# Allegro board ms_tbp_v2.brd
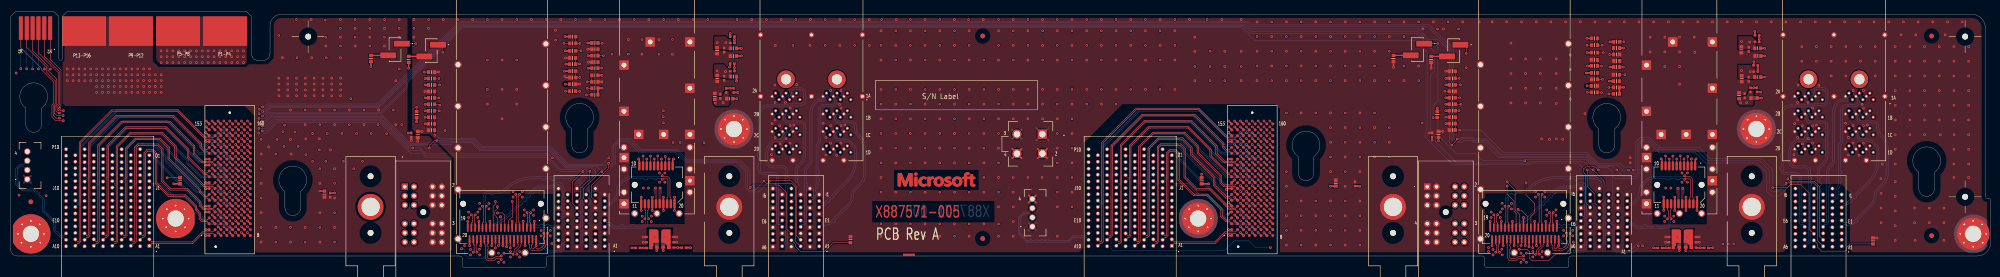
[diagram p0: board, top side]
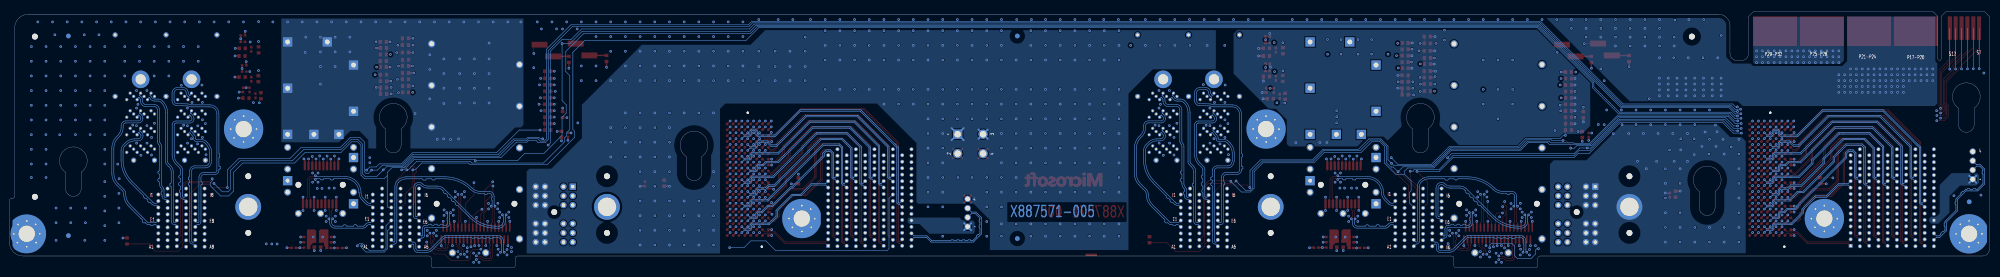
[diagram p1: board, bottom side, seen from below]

Outline 428 x 55.34 mm; copper layers: TOP, LYR2, LYR3, LYR4, LYR5, LYR6, LYR7, BOTTOM. Coordinates in mm from the lower left corner of the outline.
Outline path: 0,54.34 0,4.04 arc(0.44,2.98) 1.5,2.54 97.13,2.54 arc(97.49,2.39) 97.64,2.04 97.64,0.5 arc(97.78,0.15) 98.14,0 115.29,0 arc(115.64,0.15) 115.79,0.5 115.79,2.04 arc(115.93,2.39) 116.28,2.54 318.13,2.54 arc(318.49,2.39) 318.64,2.04 318.64,0.5 arc(318.78,0.15) 319.14,0 336.29,0 arc(336.64,0.15) 336.79,0.5 336.79,2.04 arc(336.93,2.39) 337.28,2.54 425,2.54 arc(427.12,3.42) 428,5.54 428,14.5 arc(427.85,14.85) 427.5,15 427.34,15 arc(426.99,15.15) 426.84,15.5 426.84,51.84 arc(425.96,53.96) 423.84,54.84 58.58,54.84 arc(56.81,54.11) 56.08,52.34 56.08,46.34 arc(55.64,45.28) 54.58,44.84 53.58,44.84 arc(52.52,45.28) 52.08,46.34 52.08,54.34 51.08,55.34 12.15,55.34 11.15,54.34 11.15,45.19 arc(10.8,44.84) 10.45,45.19 10.45,54.34 9.45,55.34 1,55.34 0,54.34 ; 3.3,34.53 arc(5,40) 6.7,34.53 6.7,31 arc(5,29.3) 3.3,31 3.3,34.53 ; 59.3,16.53 arc(61,22) 62.7,16.53 62.7,13 arc(61,11.3) 59.3,13 59.3,16.53 ; 121.3,30.07 arc(123,35.54) 124.7,30.07 124.7,26.54 arc(123,24.84) 121.3,26.54 121.3,30.07 ; 278.3,24.07 arc(280,29.54) 281.7,24.07 281.7,20.54 arc(280,18.84) 278.3,20.54 278.3,24.07 ; 343.3,30.07 arc(345,35.54) 346.7,30.07 346.7,26.54 arc(345,24.84) 343.3,26.54 343.3,30.07 ; 412.45,20.67 arc(414.15,26.14) 415.85,20.67 415.85,17.14 arc(414.15,15.44) 412.45,17.14 412.45,20.67

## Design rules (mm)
constraint set DEFAULT: min track width 0.102
net group DP_CLK_100M_B1<0>: nets CLK_100M_B1_N<0> CLK_100M_B1_P<0>
net group DP_CLK_100M_B1<1>: nets CLK_100M_B1_N<1> CLK_100M_B1_P<1>
net group DP_CLK_100M_B1<2>: nets CLK_100M_B1_N<2> CLK_100M_B1_P<2>
net group DP_CLK_100M_B1<3>: nets CLK_100M_B1_N<3> CLK_100M_B1_P<3>
net group DP_CLK_100M_B2<0>: nets CLK_100M_B2_N<0> CLK_100M_B2_P<0>
net group DP_CLK_100M_B2<1>: nets CLK_100M_B2_N<1> CLK_100M_B2_P<1>
net group DP_CLK_100M_B2<2>: nets CLK_100M_B2_N<2> CLK_100M_B2_P<2>
net group DP_CLK_100M_B2<3>: nets CLK_100M_B2_N<3> CLK_100M_B2_P<3>
net group DP_ETH10G_B1_RX: nets ETH10G_B1_RXN ETH10G_B1_RXP
net group DP_ETH10G_B1_TX2: nets ETH10G_B1_TXN ETH10G_B1_TXP
net group DP_ETH10G_B2_RX: nets ETH10G_B2_RXN ETH10G_B2_RXP
net group DP_ETH10G_B2_TX2: nets ETH10G_B2_TXN ETH10G_B2_TXP
net group DP_PCIE_B2T_B1_TX_D<0>: nets PCIE_B2T_B1_TX_DN<0> PCIE_B2T_B1_TX_DP<0>
net group DP_PCIE_B2T_B1_TX_D<1>: nets PCIE_B2T_B1_TX_DN<1> PCIE_B2T_B1_TX_DP<1>
net group DP_PCIE_B2T_B1_TX_D<2>: nets PCIE_B2T_B1_TX_DN<2> PCIE_B2T_B1_TX_DP<2>
net group DP_PCIE_B2T_B1_TX_D<3>: nets PCIE_B2T_B1_TX_DN<3> PCIE_B2T_B1_TX_DP<3>
net group DP_PCIE_B2T_B1_TX_D<4>: nets PCIE_B2T_B1_TX_DN<4> PCIE_B2T_B1_TX_DP<4>
net group DP_PCIE_B2T_B1_TX_D<5>: nets PCIE_B2T_B1_TX_DN<5> PCIE_B2T_B1_TX_DP<5>
net group DP_PCIE_B2T_B1_TX_D<6>: nets PCIE_B2T_B1_TX_DN<6> PCIE_B2T_B1_TX_DP<6>
net group DP_PCIE_B2T_B1_TX_D<7>: nets PCIE_B2T_B1_TX_DN<7> PCIE_B2T_B1_TX_DP<7>
net group DP_PCIE_B2T_B1_TX_D<8>: nets PCIE_B2T_B1_TX_DN<8> PCIE_B2T_B1_TX_DP<8>
net group DP_PCIE_B2T_B1_TX_D<10>: nets PCIE_B2T_B1_TX_DN<10> PCIE_B2T_B1_TX_DP<10>
net group DP_PCIE_B2T_B1_TX_D<12>: nets PCIE_B2T_B1_TX_DN<12> PCIE_B2T_B1_TX_DP<12>
net group DP_PCIE_B2T_B1_TX_D<14>: nets PCIE_B2T_B1_TX_DN<14> PCIE_B2T_B1_TX_DP<14>
net group DP_PCIE_B2T_B2_TX_D<8>: nets PCIE_B2T_B2_TX_DN<8> PCIE_B2T_B2_TX_DP<8>
net group DP_PCIE_B2T_B2_TX_D<9>: nets PCIE_B2T_B2_TX_DN<9> PCIE_B2T_B2_TX_DP<9>
net group DP_PCIE_B2T_B2_TX_D<10>: nets PCIE_B2T_B2_TX_DN<10> PCIE_B2T_B2_TX_DP<10>
net group DP_PCIE_B2T_B2_TX_D<11>: nets PCIE_B2T_B2_TX_DN<11> PCIE_B2T_B2_TX_DP<11>
net group DP_PCIE_B2T_B2_TX_D<12>: nets PCIE_B2T_B2_TX_DN<12> PCIE_B2T_B2_TX_DP<12>
net group DP_PCIE_B2T_B2_TX_D<13>: nets PCIE_B2T_B2_TX_DN<13> PCIE_B2T_B2_TX_DP<13>
net group DP_PCIE_B2T_B2_TX_D<14>: nets PCIE_B2T_B2_TX_DN<14> PCIE_B2T_B2_TX_DP<14>
net group DP_PCIE_B2T_B2_TX_D<15>: nets PCIE_B2T_B2_TX_DN<15> PCIE_B2T_B2_TX_DP<15>
net group DP_PCIE_T2B_B1_RX_D<0>: nets PCIE_T2B_B1_RX_DN<0> PCIE_T2B_B1_RX_DP<0>
net group DP_PCIE_T2B_B1_RX_D<3>: nets PCIE_T2B_B1_RX_DN<3> PCIE_T2B_B1_RX_DP<3>
net group DP_PCIE_T2B_B1_RX_D<8>: nets PCIE_T2B_B1_RX_DN<8> PCIE_T2B_B1_RX_DP<8>
net group DP_PCIE_T2B_B1_RX_D<15>: nets PCIE_T2B_B1_RX_DN<15> PCIE_T2B_B1_RX_DP<15>
net group DP_PCIE_T2B_B2_RX_D<0>: nets PCIE_T2B_B2_RX_DN<0> PCIE_T2B_B2_RX_DP<0>
net group DP_PCIE_T2B_B2_RX_D<2>: nets PCIE_T2B_B2_RX_DN<2> PCIE_T2B_B2_RX_DP<2>
net group DP_PCIE_T2B_B2_RX_D<4>: nets PCIE_T2B_B2_RX_DN<4> PCIE_T2B_B2_RX_DP<4>
net group DP_PCIE_T2B_B2_RX_D<6>: nets PCIE_T2B_B2_RX_DN<6> PCIE_T2B_B2_RX_DP<6>
net group DP_PCIE_T2B_B2_RX_D<8>: nets PCIE_T2B_B2_RX_DN<8> PCIE_T2B_B2_RX_DP<8>
net group DP_PCIE_T2B_B2_RX_D<9>: nets PCIE_T2B_B2_RX_DN<9> PCIE_T2B_B2_RX_DP<9>
net group DP_PCIE_T2B_B2_RX_D<10>: nets PCIE_T2B_B2_RX_DN<10> PCIE_T2B_B2_RX_DP<10>
net group DP_PCIE_T2B_B2_RX_D<12>: nets PCIE_T2B_B2_RX_DN<12> PCIE_T2B_B2_RX_DP<12>
net group DP_PCIE_T2B_B2_RX_D<13>: nets PCIE_T2B_B2_RX_DN<13> PCIE_T2B_B2_RX_DP<13>
net group DP_PCIE_T2B_B2_RX_D<14>: nets PCIE_T2B_B2_RX_DN<14> PCIE_T2B_B2_RX_DP<14>
net group DP_PCIE_T2B_B2_RX_D<15>: nets PCIE_T2B_B2_RX_DN<15> PCIE_T2B_B2_RX_DP<15>
net group MG_SAS_B1_RX1: nets SAS_B1_RX1N SAS_B1_RX1P
net group MG_SAS_B1_TX1: nets SAS_B1_TX3N SAS_B1_TX3P
net group USB_B1: nets USB_B1_N USB_B1_P
net group USB_B2: nets USB_B2_N USB_B2_P
net group BLADE_B1_MATED_N: nets BLADE_B1_MATED_N<1>
net group BLADE_B2_MATED_N: nets BLADE_B2_MATED_N
net group BLADE_MATED_B1_N: nets BLADE_MATED_B1_N<0>
net group BLADE_MATED_B2_N: nets BLADE_MATED_B2_N<0>
net group DP_ETH40G_B2_RX0: nets ETH40G_B2_RX0N
net group MG_ETH40G_B1_RX: nets ETH40G_B1_RX0N ETH40G_B1_RX0P ETH40G_B1_RX1N ETH40G_B1_RX1P ETH40G_B1_RX2N ETH40G_B1_RX2P ETH40G_B1_RX3N ETH40G_B1_RX3P
net group MG_ETH40G_B1_TX: nets ETH40G_B1_TX0N ETH40G_B1_TX0P ETH40G_B1_TX1N ETH40G_B1_TX1P ETH40G_B1_TX2N ETH40G_B1_TX2P ETH40G_B1_TX3N ETH40G_B1_TX3P
net group MG_ETH40G_B2_RX: nets ETH40G_B2_RX0P ETH40G_B2_RX1N ETH40G_B2_RX1P ETH40G_B2_RX2N ETH40G_B2_RX2P ETH40G_B2_RX3N ETH40G_B2_RX3P
net group MG_ETH40G_B2_TX: nets ETH40G_B2_TX0N ETH40G_B2_TX0P ETH40G_B2_TX1N ETH40G_B2_TX1P ETH40G_B2_TX2N ETH40G_B2_TX2P ETH40G_B2_TX3N ETH40G_B2_TX3P
net group MG_PCIE_B2T_B1_TX: nets PCIE_B2T_B1_TX_DN<9> PCIE_B2T_B1_TX_DN<11> PCIE_B2T_B1_TX_DN<13> PCIE_B2T_B1_TX_DN<15> PCIE_B2T_B1_TX_DP<9> PCIE_B2T_B1_TX_DP<11> PCIE_B2T_B1_TX_DP<13> PCIE_B2T_B1_TX_DP<15>
net group MG_PCIE_B2T_B2_TX: nets PCIE_B2T_B2_TX_DN<0> PCIE_B2T_B2_TX_DN<1> PCIE_B2T_B2_TX_DN<2> PCIE_B2T_B2_TX_DN<3> PCIE_B2T_B2_TX_DN<4> PCIE_B2T_B2_TX_DN<5> PCIE_B2T_B2_TX_DN<6> PCIE_B2T_B2_TX_DN<7> PCIE_B2T_B2_TX_DP<0> PCIE_B2T_B2_TX_DP<1> PCIE_B2T_B2_TX_DP<2> PCIE_B2T_B2_TX_DP<3> PCIE_B2T_B2_TX_DP<4> PCIE_B2T_B2_TX_DP<5> PCIE_B2T_B2_TX_DP<6> PCIE_B2T_B2_TX_DP<7>
net group MG_PCIE_T2B_B1_RX: nets PCIE_T2B_B1_RX_DN<1> PCIE_T2B_B1_RX_DN<2> PCIE_T2B_B1_RX_DN<4> PCIE_T2B_B1_RX_DN<5> PCIE_T2B_B1_RX_DN<6> PCIE_T2B_B1_RX_DN<7> PCIE_T2B_B1_RX_DN<9> PCIE_T2B_B1_RX_DN<10> PCIE_T2B_B1_RX_DN<11> PCIE_T2B_B1_RX_DN<12> PCIE_T2B_B1_RX_DN<13> PCIE_T2B_B1_RX_DN<14> PCIE_T2B_B1_RX_DP<1> PCIE_T2B_B1_RX_DP<2> PCIE_T2B_B1_RX_DP<4> PCIE_T2B_B1_RX_DP<5> PCIE_T2B_B1_RX_DP<6> PCIE_T2B_B1_RX_DP<7> PCIE_T2B_B1_RX_DP<9> PCIE_T2B_B1_RX_DP<10> PCIE_T2B_B1_RX_DP<11> PCIE_T2B_B1_RX_DP<12> PCIE_T2B_B1_RX_DP<13> PCIE_T2B_B1_RX_DP<14>
net group MG_PCIE_T2B_B2_RX: nets PCIE_T2B_B2_RX_DN<1> PCIE_T2B_B2_RX_DN<3> PCIE_T2B_B2_RX_DN<5> PCIE_T2B_B2_RX_DN<7> PCIE_T2B_B2_RX_DN<11> PCIE_T2B_B2_RX_DP<1> PCIE_T2B_B2_RX_DP<3> PCIE_T2B_B2_RX_DP<5> PCIE_T2B_B2_RX_DP<7> PCIE_T2B_B2_RX_DP<11>
net group MG_SAS_B1_RX2: nets SAS_B1_RX6N SAS_B1_RX6P SAS_B1_RX7N SAS_B1_RX7P
net group MG_SAS_B2_RX1: nets SAS_B2_RX1N SAS_B2_RX1P SAS_B2_RX2N SAS_B2_RX2P SAS_B2_RX3N SAS_B2_RX3P SAS_B2_RX4N SAS_B2_RX4P
net group MG_SAS_B2_RX2: nets SAS_B2_RX5N SAS_B2_RX5P SAS_B2_RX6N SAS_B2_RX6P SAS_B2_RX7N SAS_B2_RX7P SAS_B2_RX8N SAS_B2_RX8P
net group MG_SAS_B2_TX1: nets SAS_B2_TX1N SAS_B2_TX1P SAS_B2_TX2N SAS_B2_TX2P SAS_B2_TX3N SAS_B2_TX3P SAS_B2_TX4N SAS_B2_TX4P
net group MG_SAS_B2_TX2: nets SAS_B2_TX5N SAS_B2_TX5P SAS_B2_TX6N SAS_B2_TX6P SAS_B2_TX7N SAS_B2_TX7P SAS_B2_TX8N SAS_B2_TX8P
net group PCIE_RESET_B1_N: nets PCIE_RESET_B1_N<0> PCIE_RESET_B1_N<1> PCIE_RESET_B1_N<2> PCIE_RESET_B1_N<3>
net group PCIE_RESET_B2_N: nets PCIE_RESET_B2_N<0> PCIE_RESET_B2_N<1> PCIE_RESET_B2_N<2> PCIE_RESET_B2_N<3>

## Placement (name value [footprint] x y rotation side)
C1  -  [CAP_0603_CO]  88.01 28.83 90 top
C2  -  [CAP_0603_CO]  67.85 15.94 90 top
C3  -  [CAP_0402_CO]  69.07 15.71 90 top
C4  -  [CAP_0402_CO]  86.61 28.7 90 top
C5  -  [CAP_0402_CO]  142.85 6.65 0 top
C6  -  [CAP_0402_CO]  142.85 5.51 0 top
C7  -  [CAP_0402_CO]  137.9 6.65 180 top
C8  -  [CAP_0402_CO]  137.9 5.51 180 top
C9  -  [CAP_0402_CO]  363.85 6.65 0 top
C10  -  [CAP_0402_CO]  363.85 5.51 0 top
C11  -  [CAP_0402_CO]  358.9 6.65 180 top
C12  -  [CAP_0402_CO]  358.9 5.51 180 top
C13  -  [CAP_0603_CO]  308.64 28.85 90 top
C14  -  [CAP_0603_CO]  286.44 18.3 90 top
C15  -  [CAP_0402_CO]  307.24 28.73 90 top
C16  -  [CAP_0402_CO]  290.58 18.12 90 top
C17  -  [CAP_0402_CO]  374.8 37.21 90 top
C18  -  [CAP_0603_CO]  373.6 37.21 90 top
C19  -  [CAP_0402_CO]  375.69 40.77 270 top
C20  -  [CAP_0402_CO]  375.69 47.24 270 top
C23  -  [CAP_0603_CO]  374.17 40.88 270 top
C24  -  [CAP_0603_CO]  374.1 47.13 270 top
C27  -  [CAP_0603_CO]  377.68 45.81 180 top
C29  -  [CAP_0402_CO]  153.42 37.08 90 top
C30  -  [CAP_0603_CO]  152.22 37.08 90 top
C31  -  [CAP_0402_CO]  154.24 40.98 270 top
C32  -  [CAP_0402_CO]  154.24 47.08 270 top
C35  -  [CAP_0603_CO]  152.74 40.96 270 top
C36  -  [CAP_0603_CO]  152.71 46.95 270 top
C39  -  [CAP_0603_CO]  156.24 45.78 180 top
FB1  -  [FB_0402_CO]  137.98 4.28 0 top
FB2  -  [FB_0402_CO]  142.85 4.37 0 top
FB3  -  [FB_0402_CO]  358.99 4.28 0 top
FB4  -  [FB_0402_CO]  363.85 4.37 0 top
FB5  -  [FB_0402_CO]  377.21 42.42 180 top
FB6  -  [FB_0402_CO]  377.5 48.86 180 top
FB7  -  [FB_0402_CO]  376.07 38.48 90 top
FB8  -  [FB_0402_CO]  156.01 42.53 180 top
FB9  -  [FB_0402_CO]  156.01 48.63 180 top
FB10  -  [FB_0402_CO]  154.69 38.35 90 top
FS1  -  [RES_0402_CO]  135.57 4.31 0 top
FS2  -  [RES_0402_CO]  145.52 4.36 0 top
FS3  -  [RES_0402_CO]  356.5 4.28 0 top
FS4  -  [RES_0402_CO]  366.53 4.31 0 top
FS5  -  [RES_0402_CO]  377.2 43.78 0 top
FS6  -  [RES_0402_CO]  377.5 50.25 0 top
FS7  -  [RES_0402_CO]  377.46 38.48 270 top
FS8  -  [RES_0402_CO]  155.99 44.16 0 top
FS9  -  [RES_0402_CO]  156.01 50 0 top
FS10  -  [RES_0402_CO]  156.27 38.37 270 top
J1  -  [CONN_RCPT_AIRMAX_155P_35P8X19P9X20P05_2MM_RT]  30 4.74 180 top
J2  -  [CONN_RCPT_160P_8X20_32P05X10P74X6P68_1P27MM_CO]  47.38 19.04 90 top
J3  -  [GUIDEPIN_53P53X10P65X14P8MM_RT]  77.81 13.17 180 top
J4  -  [CONN_RCPT_AIRMAX_24P_29P3X11P85X10P5_2MM_RT]  85.21 17.54 0 top
J5  -  [CONN_RCPT_SFP_20P_11X7P7X5P45_P8MM_CO_RT]  139.71 17.94 180 top
J6  -  [CONN_HSNG_SFP_20P_48P72X16P2X10P05MM]  139.71 17.94 180 top
J7  -  [CONN_RCPT_AIRMAX_57P_27P3X11P9X11P65_2MM_RT]  128.42 4.64 180 top
J8  -  [CONN_RCPT_SFP_38P_18P2X11P5X5P48_P8MM_CO_RT]  106.21 10.99 180 top
J9  -  [CONN_HSNG_SFP_12P_58P72X21P95X14P1MM]  106.21 10.99 180 top
J10  -  [GUIDEPIN_53P53X10P65X14P8MM_RT]  155.35 13.17 180 top
J11  -  [CONN_RCPT_AIRMAX_57P_27P3X11P9X11P65_2MM_RT]  174.78 4.64 180 top
J12  -  [CONN_MINI_SAS_82P_38X22P25X12P24MM_RT]  181.61 36.36 180 top
J13  -  [CONN_RCPT_AIRMAX_155P_35P8X19P9X20P05_2MM_RT]  251 4.74 180 top
J14  -  [CONN_RCPT_160P_8X20_32P05X10P74X6P68_1P27MM_CO]  268.38 19.04 90 top
J15  -  [GUIDEPIN_53P53X10P65X14P8MM_RT]  298.81 13.17 180 top
J16  -  [CONN_RCPT_AIRMAX_24P_29P3X11P85X10P5_2MM_RT]  306.21 17.54 0 top
J17  -  [CONN_RCPT_SFP_20P_11X7P7X5P45_P8MM_CO_RT]  360.71 17.94 180 top
J18  -  [CONN_HSNG_SFP_20P_48P72X16P2X10P05MM]  360.71 17.94 180 top
J19  -  [CONN_RCPT_AIRMAX_57P_27P3X11P9X11P65_2MM_RT]  349.42 4.64 180 top
J20  -  [CONN_RCPT_SFP_38P_18P2X11P5X5P48_P8MM_CO_RT]  327.21 10.99 180 top
J21  -  [CONN_HSNG_SFP_12P_58P72X21P95X14P1MM]  327.21 10.99 180 top
J22  -  [GUIDEPIN_53P53X10P65X14P8MM_RT]  376.35 13.17 180 top
J23  -  [CONN_RCPT_AIRMAX_57P_27P3X11P9X11P65_2MM_RT]  395.78 4.64 180 top
J24  -  [CONN_MINI_SAS_82P_38X22P25X12P24MM_RT]  402.61 36.36 180 top
J25  -  [CONN_HDR_2P_1X2_5P08X2P54X9P65_2P54MM_CO]  90.91 46.98 270 top
J26  -  [CONN_HDR_2P_1X2_5P08X2P54X9P65_2P54MM_CO]  83.09 47.21 270 top
J27  -  [CONN_HDR_4P_2X2_9P6X9P6X12P8_4P2MM]  223.02 28.89 270 top
J28  -  [CONN_HDR_2P_1X2_5P08X2P54X9P65_2P54MM_CO]  311.91 46.98 270 top
J29  -  [CONN_HDR_2P_1X2_5P08X2P54X9P65_2P54MM_CO]  304.09 47.21 270 top
MH1  -  [MTG_276P138_VIA_9P]  4.4 7.34 0 top
MH2  -  [MTG_276P138_VIA_9P]  35.69 10.64 0 top
MH3  -  [MTG_276P138_VIA_9P]  156.35 30 0 top
MH4  -  [MTG_276P138_VIA_9P]  256.69 10.64 0 top
MH5  -  [MTG_276P138_VIA_9P]  377.35 30 0 top
MH6  -  [MTG_276P138_VIA_9P]  424.21 7.34 0 top
NOREF  -  [unnamed]  422.46 15.34 0 top
NOREF#2  -  [#2]  -8.96 317.97 0 top
NOREF#3  -  [#2]  0.03 4.71 0 top
NOREF#4  -  [unnamed]  210.12 50.13 0 top
NOREF#5  -  [#2]  10.81 44.84 0 top
NOREF#6  -  [#2]  10.45 54.34 0 top
NOREF#7  -  [#2]  280 26.54 0 top
NOREF#8  -  [#2]  428 5.54 0 top
NOREF#9  -  [unnamed]  64.32 50 0 top
NOREF#10  -  [#2]  352.18 0.3 0 top
NOREF#11  -  [#2]  534.27 145.48 0 top
NOREF#12  -  [#2]  426.5 2.54 0 top
NOREF#13  -  [unnamed]  415.22 50.13 0 top
NOREF#14  -  [#2]  369.79 0 0 top
NOREF#15  -  [#2]  318.65 1.33 0 top
NOREF#16  -  [#2]  530.41 318.63 0 top
NOREF#17  -  [#2]  11.15 54.34 0 top
NOREF#18  -  [#2]  524.06 304 0 top
NOREF#19  -  [#2]  336.74 1.1 0 top
NOREF#20  -  [#2]  345 31.54 0 top
NOREF#21  -  [#2]  97.64 1.03 0 top
NOREF#22  -  [#2]  5 37 0 top
NOREF#23  -  [#2]  427.56 53.76 0 top
NOREF#24  -  [#2]  5 24 0 top
NOREF#25  -  [#2]  56.08 52.34 0 top
NOREF#26  -  [#2]  61 19 0 top
NOREF#27  -  [#2]  384.6 220.41 0 top
NOREF#28  -  [#2]  427.91 14.78 0 top
NOREF#29  -  [#2]  17.11 55.39 0 top
NOREF#30  -  [#2]  191.86 17.52 0 top
NOREF#31  -  [#2]  280 26.54 0 top
NOREF#32  -  [#2]  115.78 1.03 0 top
NOREF#33  -  [#2]  422.46 50 0 top
NOREF#34  -  [#2]  0.72 55.06 0 top
NOREF#35  -  [#2]  56.61 53.88 0 top
NOREF#36  -  [#2]  -60.14 -153.2 0 top
NOREF#37  -  [#2]  422.46 50 0 top
NOREF#38  -  [unnamed]  210.12 6.31 0 top
NOREF#39  -  [#2]  262.59 48.05 0 top
NOREF#40  -  [#2]  425.5 54.84 0 top
NOREF#41  -  [#2]  414.15 23.14 0 top
NOREF#42  -  [#2]  61 19 0 top
NOREF#43  -  [#2]  1 55.34 0 top
NOREF#44  -  [#2]  117.66 -102.4 0 top
NOREF#45  -  [#2]  533.1 -27.1 0 top
NOREF#46  -  [#2]  414.15 21.14 0 top
NOREF#47  -  [#2]  52.65 45.16 0 top
NOREF#48  -  [#2]  123 31.54 0 top
NOREF#49  -  [#2]  149.43 2.39 0 top
NOREF#50  -  [#2]  426.84 51.84 0 top
NOREF#51  -  [#2]  52.08 54.34 0 top
NOREF#52  -  [#2]  123 32.54 0 top
NOREF#53  -  [#2]  397.3 220.41 0 top
NOREF#54  -  [unnamed]  415.22 6.95 0 top
NOREF#55  -  [#2]  10.92 44.86 0 top
NOREF#56  -  [unnamed]  422.46 50 0 top
NOREF#57  -  [unnamed]  4.38 14.26 0 top
NOREF#58  -  [#2]  422.46 15.34 0 top
NOREF#59  -  [unnamed]  210.12 50.13 180 bottom
NOREF#60  -  [unnamed]  4.38 14.26 180 bottom
NOREF#61  -  [unnamed]  210.12 6.31 180 bottom
NOREF#62  -  [unnamed]  415.22 6.95 180 bottom
NOREF#63  -  [unnamed]  415.22 50.13 180 bottom
R1  -  [RES_0603_CO]  181.54 6.06 270 top
R2  -  [RES_0603_CO]  126.3 41.62 180 top
R3  -  [RES_0603_CO]  126.3 40.22 0 top
R4  -  [RES_0603_CO]  121.52 42.53 0 top
R5  -  [RES_0603_CO]  121.52 41.14 180 top
R6  -  [RES_0603_CO]  90.99 31.15 0 top
R7  -  [RES_0603_CO]  90.99 29.76 180 top
R9  -  [RES_0603_CO]  86.04 45.07 270 top
R11  -  [RES_0603_CO]  77.91 45.28 270 top
R12  -  [RES_0603_CO]  121.47 39.71 0 top
R13  -  [RES_0603_CO]  139.67 5.13 90 top
R15  -  [RES_0603_CO]  121.52 48.53 0 top
R17  -  [RES_0603_CO]  141.07 5.13 270 top
R18  -  [RES_0603_CO]  126.31 48.62 0 top
R20  -  [RES_0603_CO]  126.31 45.87 0 top
R21  -  [RES_0603_CO]  126.31 47.27 180 top
R22  -  [RES_0603_CO]  126.31 43.15 0 top
R23  -  [RES_0603_CO]  126.31 44.48 180 top
R24  -  [RES_0603_CO]  121.49 44.04 0 top
R25  -  [RES_0603_CO]  121.49 45.36 180 top
R26  -  [RES_0603_CO]  126.3 37.43 180 top
R27  -  [RES_0603_CO]  121.51 46.92 0 top
R28  -  [RES_0603_CO]  126.3 38.82 180 top
R29  -  [RES_0603_CO]  121.52 50 180 top
R30  -  [RES_0603_CO]  342.34 43.66 0 top
R31  -  [RES_0603_CO]  342.34 44.98 180 top
R32  -  [RES_0603_CO]  342.37 42.15 0 top
R33  -  [RES_0603_CO]  342.37 40.75 180 top
R34  -  [RES_0603_CO]  311.61 31.18 0 top
R35  -  [RES_0603_CO]  311.61 29.78 180 top
R37  -  [RES_0603_CO]  307.04 45.07 270 top
R39  -  [RES_0603_CO]  298.91 45.28 270 top
R40  -  [RES_0603_CO]  342.32 39.33 0 top
R41  -  [RES_0603_CO]  360.67 5.13 90 top
R43  -  [RES_0603_CO]  342.37 48.15 0 top
R45  -  [RES_0603_CO]  362.07 5.13 270 top
R46  -  [RES_0603_CO]  347.17 48.87 0 top
R48  -  [RES_0603_CO]  347.17 43.41 0 top
R49  -  [RES_0603_CO]  347.17 44.73 180 top
R50  -  [RES_0603_CO]  347.1 40.35 0 top
R51  -  [RES_0603_CO]  347.1 41.74 180 top
R52  -  [RES_0603_CO]  347.13 47.52 180 top
R53  -  [RES_0603_CO]  347.13 46.13 0 top
R54  -  [RES_0603_CO]  347.1 37.6 180 top
R55  -  [RES_0603_CO]  342.36 46.54 0 top
R56  -  [RES_0603_CO]  347.1 39 180 top
R57  -  [RES_0603_CO]  342.37 49.62 180 top
R58  -  [RES_0603_CO]  377.65 41.24 180 top
R59  -  [RES_0603_CO]  377.63 47.46 180 top
R60  -  [RES_0603_CO]  376.83 36.7 0 top
R61  -  [RES_0603_CO]  311.61 32.58 180 top
R62  -  [RES_0603_CO]  311.61 40.96 0 top
R63  -  [RES_0603_CO]  311.61 42.51 180 top
R64  -  [RES_0603_CO]  311.61 36.77 0 top
R65  -  [RES_0603_CO]  311.61 38.16 0 top
R66  -  [RES_0603_CO]  342.32 37.93 0 top
R67  -  [RES_0603_CO]  311.61 33.97 0 top
R68  -  [RES_0603_CO]  311.61 35.37 0 top
R69  -  [RES_0603_CO]  311.61 39.56 0 top
R70  -  [RES_0603_CO]  308.39 33.13 270 top
R71  -  [RES_0603_CO]  402.55 5.8 270 top
R72  -  [RES_0603_CO]  156.27 41.36 180 top
R73  -  [RES_0603_CO]  156.27 47.46 180 top
R74  -  [RES_0603_CO]  155.45 36.58 0 top
R75  -  [RES_0603_CO]  90.99 32.55 180 top
R76  -  [RES_0603_CO]  90.99 36.74 0 top
R77  -  [RES_0603_CO]  90.99 38.14 180 top
R78  -  [RES_0603_CO]  90.99 40.93 0 top
R79  -  [RES_0603_CO]  90.99 42.33 0 top
R80  -  [RES_0603_CO]  121.47 38.19 0 top
R81  -  [RES_0603_CO]  90.99 33.95 0 top
R82  -  [RES_0603_CO]  90.99 35.34 0 top
R83  -  [RES_0603_CO]  90.99 39.54 0 top
R84  -  [RES_0603_CO]  87.76 33.11 90 top
R85  -  [RES_0603_CO]  36.63 18.81 90 top
R86  -  [RES_0603_CO]  257.44 18.81 90 top
U1  -  [CONN_EDGE_HPCE_20P_52P08X11MM_CO]  10.8 55.84 180 top
U2  -  [CONN_HDR_4P_1X4_10X4P7X6P1_2MM]  3.61 19.14 90 top
U3  -  [CONN_HDR_4P_1X4_10X4P7X6P1_2MM]  220.85 8.89 90 top

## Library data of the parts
C1 C2 C13 C14 = CAPN: alternate symbols: (CAP_0603_CO_MC); part number: CAPN_603-X862269-001
C3 C4 C15 C16 = CAPN: alternate symbols: (CAP_0402_CO_MC); part number: CAPN_402-X851568-001
C5 C8 C9 C12 = CAPN: alternate symbols: (CAP_0402_CO_MC); part number: CAPN_402-X802001-001
C6 C7 C10 C11 C17 C19 C20 C29 C31 C32 = CAPN: alternate symbols: (); part number: CAPN_402-X859521-001
C18 C23 C24 C27 C30 C35 C36 C39 = CAPN: alternate symbols: (CAP_0603_CO_R,CAP_0603_CO_MC); part number: CAPN_603-X882617-001
FB1-FB10 = FERRITE: alternate symbols: (); part number: FERRITE_402-X817739-001
FS1-FS10 = FUSE: alternate symbols: (); part number: FUSE_402-X812373-001,E
J1 J13 = AIRMAX_RCPT_155P: alternate symbols: (); part number: AIRMAX_RCPT_155P_TH-X886847-001
J2 J14 = 8X20RCPT: alternate symbols: (); part number: 8X20RCPT_SM-X886612-001
J3 J10 J15 J22 = GUIDEPIN: alternate symbols: (); part number: GUIDEPIN_TH-X863845-001
J4 J16 = AIRMAX_RCPT_24P: alternate symbols: (); part number: AIRMAX_RCPT_24P_TH-X863844-001
J5 J17 = SFP_RCPT_20P: alternate symbols: (CONN_RCPT_SFPA_20P_11X7P7X5P45_P8MM_CO_RT); part number: SFP_RCPT_20P_SM-X881930-001
J6 J18 = SFP_HSNG_20P: alternate symbols: (); part number: SFP_HSNG_20P_TH-X881931-001
J7 J11 J19 J23 = AIRMAX_RCPT_57P: alternate symbols: (); part number: AIRMAX_RCPT_57P_TH-X881927-001
J8 J20 = SFP_RCPT_38P: alternate symbols: (CONN_RCPT_SFPA_38P_18P2X11P5X5P48_P8MM_CO_RT); part number: SFP_RCPT_38P_SM-X886610-001
J9 J21 = SFP_HSNG_12P: alternate symbols: (CONN_HSNG_SFP_12P_58P72X19P75X9P95MM_NOHS); part number: SFP_HSNG_12P_TH-X886611-001
J12 J24 = MINI_SAS_72P_10MH: alternate symbols: (); part number: MINI_SAS_72P_10MH_TH-X881929-001
J25 J26 J28 J29 = 1X2HDR: alternate symbols: (); part number: 1X2HDR_SM-X866695-001
J27 = 2X2HDR: alternate symbols: (CONN_HDR_4P2X2_4P2X5P5MM); part number: 2X2HDR_TH-X02123-002
MH1-MH6 = STD_MTG_HOLE: alternate symbols: (MTG_276P138_VIA_9P); part number: STD_MTG_HOLE_TH-NONE,STD_276P138,E
R1 R3 R5 R7 R9 R11 R12 R21 R23 R25 R31 R33 R35 R37 R39 R40 R49 R51 R53 R63 R65 R71 R77 R79 R85 R86 = RESN: alternate symbols: (RES_0603_CO_MC); part number: RESN_603-X800588-001
R2 R4 R6 R18 R20 R22 R24 R26-R30 R32 R34 R46 R48 R50 R52 R54-R57 R62 R64 R67-R70 R76 R78 R81-R84 = RESN: alternate symbols: (RES_0603_CO_MC); part number: RESN_603-X800710-001
R13 R15 R17 R41 R43 R45 R58-R61 R66 R72-R75 R80 = RESN: alternate symbols: (RES_0603_CO_MC,RES_0603_CO_R,RES_0603_CO_LP); part number: RESN_603-X800629-001
U1 = HPCE_EDGE_32P_12S: alternate symbols: (); part number: HPCE_EDGE_32P_12S_SM-X883311-001
U2 U3 = 1X4HDR: alternate symbols: (); part number: 1X4HDR_TH-X819278-001,E

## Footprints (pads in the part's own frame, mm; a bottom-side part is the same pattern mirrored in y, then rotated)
CAP_0402_CO
  rect 0.584x0.508 smd: 1(-0.457,0) 2(0.457,0)
CAP_0603_CO
  rect 0.711x0.813 smd: 1(-0.648,0) 2(0.648,0)
CONN_EDGE_HPCE_20P_52P08X11MM_CO
  rect 9.449x6.299 smd: P1-P4(-35.56,4.65) P5-P8(-25.4,4.65) P9-P12(-15.24,4.65) P13-P16(-5.08,4.65) P17-P20(-5.08,4.65) P21-P24(-15.24,4.65) P25-P28(-25.4,4.65) P29-P32(-35.56,4.65)
  rect 0.813x5.004 smd: S1(2.23,4) S2(3.5,4) S3(4.77,4) S4(6.04,4) S5(7.31,4) S6(8.58,4) S7(8.58,4) S8(7.31,4) S9(6.04,4) S10(4.77,4) S11(3.5,4) S12(2.23,4)
CONN_HDR_2P_1X2_5P08X2P54X9P65_2P54MM_CO
  rect 1.27x3.429 smd: 1(-1.27,1.46) 2(1.27,-1.46)
CONN_HDR_4P_1X4_10X4P7X6P1_2MM
  round 1.372 hole 1.016: 1(0,0) 2(2,0) 3(4,0) 4(6,0)
CONN_HDR_4P_2X2_9P6X9P6X12P8_4P2MM
  rect 2.007x2.007 hole 1.397: 1(0,0)
  round 2.007 hole 1.397: 2(4.2,0) 3(0,-5.5) 4(4.2,-5.5)
CONN_HSNG_SFP_12P_58P72X21P95X14P1MM
  round 1.549 hole 1.041: 1(-9.5,0.25) 2(-9.5,-10.45) 3(-9.5,-19.45) 4(-9.5,-28.45) 5(-9.5,-37.45) 6(-5,7.75) 7(2.2,7.75) 8(9.5,4.75) 9(9.5,-5.95) 10(9.5,-14.95) 11(9.5,-23.95) 12(9.5,-32.95)
CONN_HSNG_SFP_20P_48P72X16P2X10P05MM
  round 1.473 hole 0.965: 1(0,6.2) 2(-4.8,6.2) 3(4.8,6.2) 5(-7.125,1.6) 6(7.125,1.6) 8(-7.125,-3.4) 9(7.125,-3.4) 11(-7.125,-8.1) 12(7.125,-8.1)
  rect 2.007x2.007 hole 1.041: 4(7.125,4.1) 10(7.125,-5.9) 13(-7.125,-10.9) 14(-1.445,-10.9) 15(3.955,-10.9) 16(7.125,-15.9) 17(-7.125,-20.9) 18(7.125,-25.9) 19(-7.125,-30.9) 20(1.455,-30.9)
  rect 2.007x2.007 hole 0.838: 7(-7.125,-0.9)
CONN_MINI_SAS_82P_38X22P25X12P24MM_RT
  round 3.81 hole 2.21: (3,-4.4) (14,-4.4)
  round 1.118 hole 0.61: 1(1.5,13.11) 2(6,13.11) 3(12.5,13.11) 4(17,13.11) 5(-2.5,-0.7) 6(8.5,-0.7) 7(19.5,-0.7) 8(-2.5,-14.01) 9(8.5,-14.01) 10(19.5,-14.01)
  round 0.686 hole 0.381: 1A1(0,0) 1A2(0.75,-1.4) 1A3(1.5,-0.7) 1A4(2.25,0) 1A5(3,-1.4) 1A6(3.75,-0.7) 1A7(4.5,0) 1A8(5.25,-1.4) 1A9(6,-0.7) 1B1(0,3.8) 1B2(0.75,2.4) 1B3(1.5,3.1) 1B4(2.25,3.8) 1B5(3,2.4) 1B6(3.75,3.1) 1B7(4.5,3.8) 1B8(5.25,2.4) 1B9(6,3.1) 1C1(0,7.6) 1C2(0.75,6.2) 1C3(1.5,6.9) 1C4(2.25,7.6) 1C5(3,6.2) 1C6(3.75,6.9) 1C7(4.5,7.6) 1C8(5.25,6.2) 1C9(6,6.9) 1D1(0,11.4) 1D2(0.75,10) 1D3(1.5,10.7) 1D4(2.25,11.4) 1D5(3,10) 1D6(3.75,10.7) 1D7(4.5,11.4) 1D8(5.25,10) 1D9(6,10.7) 2A1(11,0) 2A2(11.75,-1.4) 2A3(12.5,-0.7) 2A4(13.25,0) 2A5(14,-1.4) 2A6(14.75,-0.7) 2A7(15.5,0) 2A8(16.25,-1.4) 2A9(17,-0.7) 2B1(11,3.8) 2B2(11.75,2.4) 2B3(12.5,3.1) 2B4(13.25,3.8) 2B5(14,2.4) 2B6(14.75,3.1) 2B7(15.5,3.8) 2B8(16.25,2.4) 2B9(17,3.1) 2C1(11,7.6) 2C2(11.75,6.2) 2C3(12.5,6.9) 2C4(13.25,7.6) 2C5(14,6.2) 2C6(14.75,6.9) 2C7(15.5,7.6) 2C8(16.25,6.2) 2C9(17,6.9) 2D1(11,11.4) 2D2(11.75,10) 2D3(12.5,10.7) 2D4(13.25,11.4) 2D5(14,10) 2D6(14.75,10.7) 2D7(15.5,11.4) 2D8(16.25,10) 2D9(17,10.7)
CONN_RCPT_160P_8X20_32P05X10P74X6P68_1P27MM_CO
  round 0.508 hole 1.27 unplated: (-14.491,3.048) (14.491,0)
  round 0.635 smd: 1(-12.065,4.445) 2(-12.065,3.175) 3(-12.065,1.905) 4(-12.065,0.635) 5(-12.065,-0.635) 6(-12.065,-1.905) 7(-12.065,-3.175) 8(-12.065,-4.445) 9(-10.795,4.445) 10(-10.795,3.175) 11(-10.795,1.905) 12(-10.795,0.635) 13(-10.795,-0.635) 14(-10.795,-1.905) 15(-10.795,-3.175) 16(-10.795,-4.445) 17(-9.525,4.445) 18(-9.525,3.175) 19(-9.525,1.905) 20(-9.525,0.635) 21(-9.525,-0.635) 22(-9.525,-1.905) 23(-9.525,-3.175) 24(-9.525,-4.445) 25(-8.255,4.445) 26(-8.255,3.175) 27(-8.255,1.905) 28(-8.255,0.635) 29(-8.255,-0.635) 30(-8.255,-1.905) 31(-8.255,-3.175) 32(-8.255,-4.445) 33(-6.985,4.445) 34(-6.985,3.175) 35(-6.985,1.905) 36(-6.985,0.635) 37(-6.985,-0.635) 38(-6.985,-1.905) 39(-6.985,-3.175) 40(-6.985,-4.445) 41(-5.715,4.445) 42(-5.715,3.175) 43(-5.715,1.905) 44(-5.715,0.635) 45(-5.715,-0.635) 46(-5.715,-1.905) 47(-5.715,-3.175) 48(-5.715,-4.445) 49(-4.445,4.445) 50(-4.445,3.175) 51(-4.445,1.905) 52(-4.445,0.635) 53(-4.445,-0.635) 54(-4.445,-1.905) 55(-4.445,-3.175) 56(-4.445,-4.445) 57(-3.175,4.445) 58(-3.175,3.175) 59(-3.175,1.905) 60(-3.175,0.635) 61(-3.175,-0.635) 62(-3.175,-1.905) 63(-3.175,-3.175) 64(-3.175,-4.445) 65(-1.905,4.445) 66(-1.905,3.175) 67(-1.905,1.905) 68(-1.905,0.635) 69(-1.905,-0.635) 70(-1.905,-1.905) 71(-1.905,-3.175) 72(-1.905,-4.445) 73(-0.635,4.445) 74(-0.635,3.175) 75(-0.635,1.905) 76(-0.635,0.635) 77(-0.635,-0.635) 78(-0.635,-1.905) 79(-0.635,-3.175) 80(-0.635,-4.445) 81(0.635,4.445) 82(0.635,3.175) 83(0.635,1.905) 84(0.635,0.635) 85(0.635,-0.635) 86(0.635,-1.905) 87(0.635,-3.175) 88(0.635,-4.445) 89(1.905,4.445) 90(1.905,3.175) 91(1.905,1.905) 92(1.905,0.635) 93(1.905,-0.635) 94(1.905,-1.905) 95(1.905,-3.175) 96(1.905,-4.445) 97(3.175,4.445) 98(3.175,3.175) 99(3.175,1.905) 100(3.175,0.635) 101(3.175,-0.635) 102(3.175,-1.905) 103(3.175,-3.175) 104(3.175,-4.445) 105(4.445,4.445) 106(4.445,3.175) 107(4.445,1.905) 108(4.445,0.635) 109(4.445,-0.635) 110(4.445,-1.905) 111(4.445,-3.175) 112(4.445,-4.445) 113(5.715,4.445) 114(5.715,3.175) 115(5.715,1.905) 116(5.715,0.635) 117(5.715,-0.635) 118(5.715,-1.905) 119(5.715,-3.175) 120(5.715,-4.445) 121(6.985,4.445) 122(6.985,3.175) 123(6.985,1.905) 124(6.985,0.635) 125(6.985,-0.635) 126(6.985,-1.905) 127(6.985,-3.175) 128(6.985,-4.445) 129(8.255,4.445) 130(8.255,3.175) 131(8.255,1.905) 132(8.255,0.635) 133(8.255,-0.635) 134(8.255,-1.905) 135(8.255,-3.175) 136(8.255,-4.445) 137(9.525,4.445) 138(9.525,3.175) 139(9.525,1.905) 140(9.525,0.635) 141(9.525,-0.635) 142(9.525,-1.905) 143(9.525,-3.175) 144(9.525,-4.445) 145(10.795,4.445) 146(10.795,3.175) 147(10.795,1.905) 148(10.795,0.635) 149(10.795,-0.635) 150(10.795,-1.905) 151(10.795,-3.175) 152(10.795,-4.445) 153(12.065,4.445) 154(12.065,3.175) 155(12.065,1.905) 156(12.065,0.635) 157(12.065,-0.635) 158(12.065,-1.905) 159(12.065,-3.175) 160(12.065,-4.445)
CONN_RCPT_AIRMAX_24P_29P3X11P85X10P5_2MM_RT
  round 1.27 hole 2.184 unplated: (4,-5.5)
  rect 1.372x1.372 hole 0.762: 1A(0,0)
  round 1.372 hole 0.762: 1B(2,0) 1C(0,-2) 1D(2,-2) 1E(0,-4) 1F(2,-4) 2A(6,0) 2B(8,0) 2C(6,-2) 2D(8,-2) 2E(6,-4) 2F(8,-4) 3A(6,-8) 3B(8,-8) 3C(6,-10) 3D(8,-10) 3E(6,-12) 3F(8,-12) 4A(0,-8) 4B(2,-8) 4C(0,-10) 4D(2,-10) 4E(0,-12) 4F(2,-12)
CONN_RCPT_AIRMAX_57P_27P3X11P9X11P65_2MM_RT
  round 0.813 hole 0.508: A1(0,0) A2(2,0.1) A3(4,0) A4(6,0.1) A5(8,0) A6(10,0.1) B1(0,-1.4) B2(2,-1.3) B3(4,-1.4) B4(6,-1.3) B5(8,-1.4) B6(10,-1.3) C1(0,-2.8) C2(2,-2.7) C3(4,-2.8) C4(6,-2.7) C5(8,-2.8) C6(10,-2.7) D1(0,-4.2) D2(2,-4.1) D3(4,-4.2) D4(6,-4.1) D5(8,-4.2) D6(10,-4.1) E1(0,-5.6) E2(2,-5.5) E3(4,-5.6) E4(6,-5.5) E5(8,-5.6) E6(10,-5.5) F1(0,-7) F2(2,-6.9) F3(4,-7) F4(6,-6.9) F5(8,-7) F6(10,-6.9) G1(0,-8.4) G2(2,-8.3) G3(4,-8.4) G4(6,-8.3) G5(8,-8.4) G6(10,-8.3) H1(0,-9.8) H2(2,-9.7) H3(4,-9.8) H4(6,-9.7) H5(8,-9.8) H6(10,-9.7) I1(0,-11.2) I2(2,-11.1) I3(4,-11.2) I4(6,-11.1) I5(8,-11.2) I6(10,-11.1) J2(2,-12.5) J4(6,-12.5) J6(10,-12.5)
CONN_RCPT_AIRMAX_155P_35P8X19P9X20P05_2MM_RT
  rect 0.813x0.813 hole 0.508: A1(0,0)
  round 0.813 hole 0.508: A2(2,0.1) A3(4,0) A4(6,0.1) A5(8,0) A6(10,0.1) A7(12,0) A8(14,0.1) A9(16,0) A10(18,0.1) B1(0,-1.4) B2(2,-1.3) B3(4,-1.4) B4(6,-1.3) B5(8,-1.4) B6(10,-1.3) B7(12,-1.4) B8(14,-1.3) B9(16,-1.4) B10(18,-1.3) C1(0,-2.8) C2(2,-2.7) C3(4,-2.8) C4(6,-2.7) C5(8,-2.8) C6(10,-2.7) C7(12,-2.8) C8(14,-2.7) C9(16,-2.8) C10(18,-2.7) D1(0,-4.2) D2(2,-4.1) D3(4,-4.2) D4(6,-4.1) D5(8,-4.2) D6(10,-4.1) D7(12,-4.2) D8(14,-4.1) D9(16,-4.2) D10(18,-4.1) E1(0,-5.6) E2(2,-5.5) E3(4,-5.6) E4(6,-5.5) E5(8,-5.6) E6(10,-5.5) E7(12,-5.6) E8(14,-5.5) E9(16,-5.6) E10(18,-5.5) F1(0,-7) F2(2,-6.9) F3(4,-7) F4(6,-6.9) F5(8,-7) F6(10,-6.9) F7(12,-7) F8(14,-6.9) F9(16,-7) F10(18,-6.9) G1(0,-8.4) G2(2,-8.3) G3(4,-8.4) G4(6,-8.3) G5(8,-8.4) G6(10,-8.3) G7(12,-8.4) G8(14,-8.3) G9(16,-8.4) G10(18,-8.3) H1(0,-9.8) H2(2,-9.7) H3(4,-9.8) H4(6,-9.7) H5(8,-9.8) H6(10,-9.7) H7(12,-9.8) H8(14,-9.7) H9(16,-9.8) H10(18,-9.7) I1(0,-11.2) I2(2,-11.1) I3(4,-11.2) I4(6,-11.1) I5(8,-11.2) I6(10,-11.1) I7(12,-11.2) I8(14,-11.1) I9(16,-11.2) I10(18,-11.1) J1(0,-12.6) J2(2,-12.5) J3(4,-12.6) J4(6,-12.5) J5(8,-12.6) J6(10,-12.5) J7(12,-12.6) J8(14,-12.5) J9(16,-12.6) J10(18,-12.5) K1(0,-14) K2(2,-13.9) K3(4,-14) K4(6,-13.9) K5(8,-14) K6(10,-13.9) K7(12,-14) K8(14,-13.9) K9(16,-14) K10(18,-13.9) L1(0,-15.4) L2(2,-15.3) L3(4,-15.4) L4(6,-15.3) L5(8,-15.4) L6(10,-15.3) L7(12,-15.4) L8(14,-15.3) L9(16,-15.4) L10(18,-15.3) M1(0,-16.8) M2(2,-16.7) M3(4,-16.8) M4(6,-16.7) M5(8,-16.8) M6(10,-16.7) M7(12,-16.8) M8(14,-16.7) M9(16,-16.8) M10(18,-16.7) N1(0,-18.2) N2(2,-18.1) N3(4,-18.2) N4(6,-18.1) N5(8,-18.2) N6(10,-18.1) N7(12,-18.2) N8(14,-18.1) N9(16,-18.2) N10(18,-18.1) O1(0,-19.6) O2(2,-19.5) O3(4,-19.6) O4(6,-19.5) O5(8,-19.6) O6(10,-19.5) O7(12,-19.6) O8(14,-19.5) O9(16,-19.6) O10(18,-19.5) P2(2,-20.9) P4(6,-20.9) P6(10,-20.9) P8(14,-20.9) P10(18,-20.9)
CONN_RCPT_SFP_20P_11X7P7X5P45_P8MM_CO_RT
  round 1.27 hole 1.6 unplated: (-4.8,0) (4.8,0)
  oval 0.508x2.007 smd: 1(-3.4,-4.1) 2(-2.6,-4.1) 3(-1.8,-4.1) 4(-1,-4.1) 5(-0.2,-4.1) 6(0.6,-4.1) 7(1.4,-4.1) 8(2.2,-4.1) 9(3,-4.1) 10(3.8,-4.1) 11(3.4,4.1) 12(2.6,4.1) 13(1.8,4.1) 14(1,4.1) 15(0.2,4.1) 16(-0.6,4.1) 17(-1.4,4.1) 18(-2.2,4.1) 19(-3,4.1) 20(-3.8,4.1)
CONN_RCPT_SFP_38P_18P2X11P5X5P48_P8MM_CO_RT
  round 1.27 hole 1.549 unplated: (-8.4,-2.85) (8.4,-2.85)
  oval 0.356x1.803 smd: 1(-7,2.33) 2(-6.2,2.33) 3(-5.4,2.33) 4(-4.6,2.33) 5(-3.8,2.33) 6(-3,2.33) 7(-2.2,2.33) 8(-1.4,2.33) 9(-0.6,2.33) 10(0.2,2.33) 11(1,2.33) 12(1.8,2.33) 13(2.6,2.33) 14(3.4,2.33) 15(4.2,2.33) 16(5,2.33) 17(5.8,2.33) 18(6.6,2.33) 19(7.4,2.33) 20(7,4.83) 21(6.2,4.83) 22(5.4,4.83) 23(4.6,4.83) 24(3.8,4.83) 25(3,4.83) 26(2.2,4.83) 27(1.4,4.83) 28(0.6,4.83) 29(-0.2,4.83) 30(-1,4.83) 31(-1.8,4.83) 32(-2.6,4.83) 33(-3.4,4.83) 34(-4.2,4.83) 35(-5,4.83) 36(-5.8,4.83) 37(-6.6,4.83) 38(-7.4,4.83)
FB_0402_CO
  rect 0.584x0.508 smd: 1(-0.457,0) 2(0.457,0)
GUIDEPIN_53P53X10P65X14P8MM_RT
  round 1.27 hole 3.962 unplated: (0,5.63) (0,-6.62)
  round 5.588 hole 3.962: 1(0,0)
MTG_276P138_VIA_9P
  round 7.01 hole 3.505: 1(0,0)
  round 0.66 hole 0.356: 2(0,2.794) 3(-1.905,2.032) 4(-2.794,0) 5(-2.032,-1.905) 6(0,-2.794) 7(2.032,-1.905) 8(2.794,0) 9(1.905,2.032)
RES_0402_CO
  rect 0.584x0.508 smd: 1(-0.46,0) 2(0.46,0)
RES_0603_CO
  rect 0.711x0.813 smd: 1(-0.65,0) 2(0.65,0)
unnamed
  round 1.27 hole 3.175 unplated: (0,0)

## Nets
GND: C1.2(B<0>) C2.2(B<0>) C3.2(B<0>) C4.2(B<0>) C5.2(B<0>) C6.2(B<0>) C7.2(B<0>) C8.2(B<0>) C9.2(B<0>) C10.2(B<0>) C11.2(B<0>) C12.2(B<0>) C13.2(B<0>) C14.2(B<0>) C15.2(B<0>) C16.2(B<0>) C17.2(B<0>) C18.2(B<0>) C19.2(B<0>) C20.2(B<0>) C23.2(B<0>) C24.2(B<0>) C27.2(B<0>) C29.2(B<0>) C30.2(B<0>) C31.2(B<0>) C32.2(B<0>) C35.2(B<0>) C36.2(B<0>) C39.2(B<0>) J1.A2 J1.A4 J1.A6 J1.A8 J1.A10 J1.C1 J1.C3 J1.C5 J1.C7 J1.C9 J1.D2 J1.D4 J1.D6 J1.D8 J1.D10 J1.F1 J1.F3 J1.F5 J1.F7 J1.F9 J1.F10 J1.G2 J1.G4 J1.G6 J1.G8 J1.G10 J1.H10 J1.I1 J1.I3 J1.I5 J1.I7 J1.I9 J1.J2 J1.J4 J1.J6 J1.J8 J1.L1 J1.L3 J1.L5 J1.L7 J1.L9 J1.M2 J1.M4 J1.M6 J1.M8 J1.M9 J1.M10 J1.N9 J1.O1 J1.O3 J1.O5 J1.O7 J1.O9 J1.P2 J1.P4 J1.P6 J1.P8 J1.P10 J2.1 J2.3 J2.5 J2.7 J2.9 J2.11 J2.13 J2.15 J2.18 J2.20 J2.22 J2.24 J2.26 J2.28 J2.30 J2.32 J2.33 J2.35 J2.37 J2.39 J2.41 J2.43 J2.45 J2.47 J2.50 J2.52 J2.54 J2.56 J2.58 J2.60 J2.62 J2.64 J2.65 J2.67 J2.69 J2.71 J2.73 J2.75 J2.77 J2.79 J2.82 J2.84 J2.86 J2.88 J2.90 J2.92 J2.94 J2.96 J2.97 J2.99 J2.101 J2.103 J2.105 J2.107 J2.109 J2.111 J2.114 J2.116 J2.118 J2.120 J2.122 J2.124 J2.126 J2.128 J2.129 J2.131 J2.133 J2.135 J2.139 J2.141 J2.146 J2.147 J3.1(GND) J4.1A J4.1B J4.1C J4.1D J4.1E J4.1F J4.4A J4.4B J4.4C J4.4D J4.4E J4.4F J5.1(VEET1) J5.10(VEER1) J5.11(VEER2) J5.14(VEER3) J5.17(VEET2) J5.20(VEET3) J6.1(GND1) J6.2(GND2) J6.3(GND3) J6.4(GND4) J6.5(GND5) J6.6(GND6) J6.7(GND7) J6.8(GND8) J6.9(GND9) J6.10(GND10) J6.11(GND11) J6.12(GND12) J6.13(GND13) J6.14(GND14) J6.15(GND15) J6.16(GND16) J6.17(GND17) J6.18(GND18) J6.19(GND19) J6.20(GND20) J7.A2 J7.A4 J7.A6 J7.C1 J7.C3 J7.C5 J7.D2 J7.D4 J7.D6 J7.F1 J7.F5 J7.G2 J7.G6 J7.I1 J7.J2 J7.J4 J7.J6 J8.1(GND_TX_1) J8.4(GND_TX_2) J8.7(GND_TX_3) J8.13(GND_RX_1) J8.16(GND_RX_2) J8.19(GND_RX_3) J8.20(GND_RX_4) J8.23(GND_RX_5) J8.26(GND_RX_6) J8.32(GND_TX_4) J8.35(GND_TX_5) J8.38(GND_TX_6) J9.1(GND1) J9.2(GND2) J9.3(GND3) J9.4(GND4) J9.5(GND5) J9.6(GND6) J9.7(GND7) J9.8(GND8) J9.9(GND9) J9.10(GND10) J9.11(GND11) J9.12(GND12) J10.1(GND) J11.A2 J11.A4 J11.A6 J11.C1 J11.C3 J11.C5 J11.D2 J11.D4 J11.D6 J11.F1 J11.F3 J11.F5 J11.G2 J11.G4 J11.G6 J11.I1 J11.I3 J11.I5 J11.J2 J11.J4 J11.J6 J12.1(MT1) J12.1A3 J12.1A6 J12.1A9 J12.1B3 J12.1B6 J12.1B9 J12.1C3 J12.1C6 J12.1C9 J12.1D3 J12.1D6 J12.1D9 J12.2(MT2) J12.2A3 J12.2A6 J12.2A9 J12.2B3 J12.2B6 J12.2B9 J12.2C3 J12.2C6 J12.2C9 J12.2D3 J12.2D6 J12.2D9 J12.3(MT3) J12.4(MT4) J12.5(MT5) J12.6(MT6) J12.7(MT7) J12.8(MT8) J12.9(MT9) J12.10(MT10) J13.A2 J13.A4 J13.A6 J13.A8 J13.A10 J13.C1 J13.C3 J13.C5 J13.C7 J13.C9 J13.D2 J13.D4 J13.D6 J13.D8 J13.D10 J13.F1 J13.F3 J13.F5 J13.F7 J13.F9 J13.F10 J13.G2 J13.G4 J13.G6 J13.G8 J13.G10 J13.H10 J13.I1 J13.I3 J13.I5 J13.I7 J13.I9 J13.J2 J13.J4 J13.J6 J13.J8 J13.L1 J13.L3 J13.L5 J13.L7 J13.L9 J13.M2 J13.M4 J13.M6 J13.M8 J13.M9 J13.M10 J13.N9 J13.O1 J13.O3 J13.O5 J13.O7 J13.O9 J13.P2 J13.P4 J13.P6 J13.P8 J13.P10 J14.1 J14.3 J14.5 J14.7 J14.9 J14.11 J14.13 J14.15 J14.18 J14.20 J14.22 J14.24 J14.26 J14.28 J14.30 J14.32 J14.33 J14.35 J14.37 J14.39 J14.41 J14.43 J14.45 J14.47 J14.50 J14.52 J14.54 J14.56 J14.58 J14.60 J14.62 J14.64 J14.65 J14.67 J14.69 J14.71 J14.73 J14.75 J14.77 J14.79 J14.82 J14.84 J14.86 J14.88 J14.90 J14.92 J14.94 J14.96 J14.97 J14.99 J14.101 J14.103 J14.105 J14.107 J14.109 J14.111 J14.114 J14.116 J14.118 J14.120 J14.122 J14.124 J14.126 J14.128 J14.129 J14.131 J14.133 J14.135 J14.139 J14.141 J14.146 J14.147 J15.1(GND) J16.1A J16.1B J16.1C J16.1D J16.1E J16.1F J16.4A J16.4B J16.4C J16.4D J16.4E J16.4F J17.1(VEET1) J17.10(VEER1) J17.11(VEER2) J17.14(VEER3) J17.17(VEET2) J17.20(VEET3) J18.1(GND1) J18.2(GND2) J18.3(GND3) J18.4(GND4) J18.5(GND5) J18.6(GND6) J18.7(GND7) J18.8(GND8) J18.9(GND9) J18.10(GND10) J18.11(GND11) J18.12(GND12) J18.13(GND13) J18.14(GND14) J18.15(GND15) J18.16(GND16) J18.17(GND17) J18.18(GND18) J18.19(GND19) J18.20(GND20) J19.A2 J19.A4 J19.A6 J19.C1 J19.C3 J19.C5 J19.D2 J19.D4 J19.D6 J19.F1 J19.F5 J19.G2 J19.G6 J19.I1 J19.J2 J19.J4 J19.J6 J20.1(GND_TX_1) J20.4(GND_TX_2) J20.7(GND_TX_3) J20.13(GND_RX_1) J20.16(GND_RX_2) J20.19(GND_RX_3) J20.20(GND_RX_4) J20.23(GND_RX_5) J20.26(GND_RX_6) J20.32(GND_TX_4) J20.35(GND_TX_5) J20.38(GND_TX_6) J21.1(GND1) J21.2(GND2) J21.3(GND3) J21.4(GND4) J21.5(GND5) J21.6(GND6) J21.7(GND7) J21.8(GND8) J21.9(GND9) J21.10(GND10) J21.11(GND11) J21.12(GND12) J22.1(GND) J23.A2 J23.A4 J23.A6 J23.C1 J23.C3 J23.C5 J23.D2 J23.D4 J23.D6 J23.F1 J23.F3 J23.F5 J23.G2 J23.G4 J23.G6 J23.I1 J23.I3 J23.I5 J23.J2 J23.J4 J23.J6 J24.1(MT1) J24.1A3 J24.1A6 J24.1A9 J24.1B3 J24.1B6 J24.1B9 J24.1C3 J24.1C6 J24.1C9 J24.1D3 J24.1D6 J24.1D9 J24.2(MT2) J24.2A3 J24.2A6 J24.2A9 J24.2B3 J24.2B6 J24.2B9 J24.2C3 J24.2C6 J24.2C9 J24.2D3 J24.2D6 J24.2D9 J24.3(MT3) J24.4(MT4) J24.5(MT5) J24.6(MT6) J24.7(MT7) J24.8(MT8) J24.9(MT9) J24.10(MT10) J27.2(IO2) J27.4(IO4) MH1.1 MH1.2 MH1.3 MH1.4 MH1.5 MH1.6 MH1.7 MH1.8 MH1.9(NC9) MH2.1 MH2.2 MH2.3 MH2.4 MH2.5 MH2.6 MH2.7 MH2.8 MH2.9(NC9) MH3.1 MH3.2 MH3.3 MH3.4 MH3.5 MH3.6 MH3.7 MH3.8 MH3.9(NC9) MH4.1 MH4.2 MH4.3 MH4.4 MH4.5 MH4.6 MH4.7 MH4.8 MH4.9(NC9) MH5.1 MH5.2 MH5.3 MH5.4 MH5.5 MH5.6 MH5.7 MH5.8 MH5.9(NC9) MH6.1 MH6.2 MH6.3 MH6.4 MH6.5 MH6.6 MH6.7 MH6.8 MH6.9(NC9) R1.1(A<0>) R3.2(B<0>) R5.2(B<0>) R7.2(B<0>) R9.2(B<0>) R11.2(B<0>) R12.2(B<0>) R21.2(B<0>) R23.2(B<0>) R25.2(B<0>) R31.2(B<0>) R33.2(B<0>) R35.2(B<0>) R37.2(B<0>) R39.2(B<0>) R40.2(B<0>) R49.2(B<0>) R51.2(B<0>) R53.2(B<0>) R63.2(B<0>) R65.2(B<0>) R71.1(A<0>) R77.2(B<0>) R79.2(B<0>) R85.1(A<0>) R86.1(A<0>) U1.P1-P4 U1.P5-P8 U1.P25-P28 U1.P29-P32 U2.4(IO<4>) U3.4(IO<4>)
P3V3_10G_B1_VCCR: C7.1(A<0>) C8.1(A<0>) FB1.2(B) J5.15(VCCR) R13.2(B<0>)
P3V3_10G_B1_VCCT: C5.1(A<0>) C6.1(A<0>) FB2.1(A) J5.16(VCCT) R17.1(A<0>)
P3V3_10G_B2_VCCR: C11.1(A<0>) C12.1(A<0>) FB3.2(B) J17.15(VCCR) R41.2(B<0>)
P3V3_10G_B2_VCCT: C9.1(A<0>) C10.1(A<0>) FB4.1(A) J17.16(VCCT) R45.1(A<0>)
P3V3_40G_B1_VCC1: C29.1(A<0>) C30.1(A<0>) FB10.1(A) J8.30(VCC1) R74.1(A<0>)
P3V3_40G_B1_VCC_RX: C32.1(A<0>) C36.1(A<0>) FB9.2(B) J8.10(VCC_RX) R73.2(B<0>)
P3V3_40G_B1_VCC_TX: C31.1(A<0>) C35.1(A<0>) FB8.2(B) J8.29(VCC_TX) R72.2(B<0>)
P3V3_40G_B2_VCC1: C17.1(A<0>) C18.1(A<0>) FB7.1(A) J20.30(VCC1) R60.1(A<0>)
P3V3_40G_B2_VCC_RX: C20.1(A<0>) C24.1(A<0>) FB6.2(B) J20.10(VCC_RX) R59.2(B<0>)
P3V3_40G_B2_VCC_TX: C19.1(A<0>) C23.1(A<0>) FB5.2(B) J20.29(VCC_TX) R58.2(B<0>)
P3V3_B1_QSFP: C39.1(A<0>) FS1.1(A<0>) FS2.2(B<0>) FS8.1(A<0>) FS9.1(A<0>) FS10.2(B<0>) J7.D5 J7.E5 J7.I3 R2.1(A<0>) R4.1(A<0>) R6.1(A<0>) R13.1(A<0>) R17.2(B<0>) R18.1(A<0>) R20.1(A<0>) R22.1(A<0>) R24.1(A<0>) R26.1(A<0>) R27.1(A<0>) R28.1(A<0>) R29.2(B<0>) R72.1(A<0>) R73.1(A<0>) R74.2(B<0>) R76.1(A<0>) R78.1(A<0>) R81.1(A<0>) R82.1(A<0>) R83.1(A<0>) R84.1(A<0>)
P3V3_B2_QSFP: C27.1(A<0>) FS3.1(A<0>) FS4.2(B<0>) FS5.1(A<0>) FS6.1(A<0>) FS7.2(B<0>) J19.D5 J19.E5 J19.I3 R30.1(A<0>) R32.1(A<0>) R34.1(A<0>) R41.1(A<0>) R45.2(B<0>) R46.1(A<0>) R48.1(A<0>) R50.1(A<0>) R52.1(A<0>) R54.1(A<0>) R55.1(A<0>) R56.1(A<0>) R57.2(B<0>) R58.1(A<0>) R59.1(A<0>) R60.2(B<0>) R62.1(A<0>) R64.1(A<0>) R67.1(A<0>) R68.1(A<0>) R69.1(A<0>) R70.1(A<0>)
P5V_USB_B1: J1.E10 U2.1(IO<1>)
P5V_USB_B2: J13.E10 U3.1(IO<1>)
P12V: C1.1(A<0>) C2.1(A<0>) C3.1(A<0>) C4.1(A<0>) C13.1(A<0>) C14.1(A<0>) C15.1(A<0>) C16.1(A<0>) J4.2A J4.2B J4.2C J4.2D J4.2E J4.2F J4.3A J4.3B J4.3C J4.3D J4.3E J4.3F J16.2A J16.2B J16.2C J16.2D J16.2E J16.2F J16.3A J16.3B J16.3C J16.3D J16.3E J16.3F J27.1(IO1) J27.3(IO3) U1.P9-P12 U1.P13-P16 U1.P17-P20 U1.P21-P24
P12V_MEZZ_B1: J1.I10 J1.J10 J1.K10 J1.L10 J1.N10 J1.O10 J2.137 J2.145 J2.153 J2.154 J2.155
P12V_MEZZ_B2: J13.I10 J13.J10 J13.K10 J13.L10 J13.N10 J13.O10 J14.137 J14.145 J14.153 J14.154 J14.155
BLADE_B1_EN1: J7.H2 J11.C4 J25.1(IO<1>) U1.S3
BLADE_B1_MATED_N<1>: J7.I5 R12.1(A<0>)
BLADE_B2_EN1: J19.H2 J23.C4 J28.1(IO<1>) U1.S10
BLADE_B2_MATED_N: J19.I5 R40.1(A<0>)
BLADE_MATED_B1_N<0>: J1.I6 R85.2(B<0>)
BLADE_MATED_B2_N<0>: J13.I6 R86.2(B<0>)
CLK_100M_B1_N<0>: J1.B9 J2.138
CLK_100M_B1_N<1>: J1.E9 J2.140
CLK_100M_B1_N<2>: J1.H9 J2.142
CLK_100M_B1_N<3>: J1.K9 J2.144
CLK_100M_B1_P<0>: J1.A9 J2.130
CLK_100M_B1_P<1>: J1.D9 J2.132
CLK_100M_B1_P<2>: J1.G9 J2.134
CLK_100M_B1_P<3>: J1.J9 J2.136
CLK_100M_B2_N<0>: J13.B9 J14.138
CLK_100M_B2_N<1>: J13.E9 J14.140
CLK_100M_B2_N<2>: J13.H9 J14.142
CLK_100M_B2_N<3>: J13.K9 J14.144
CLK_100M_B2_P<0>: J13.A9 J14.130
CLK_100M_B2_P<1>: J13.D9 J14.132
CLK_100M_B2_P<2>: J13.G9 J14.134
CLK_100M_B2_P<3>: J13.J9 J14.136
ETH10G_B1_MOD_ABS: J5.6(MOD_ABS) R15.2(B<0>) R29.1(A<0>)
ETH10G_B1_PRES_N: J7.I2 R15.1(A<0>)
ETH10G_B1_RS0: J5.7(RS0) R22.2(B<0>) R23.1(A<0>)
ETH10G_B1_RS1: J5.9(RS1) R24.2(B<0>) R25.1(A<0>)
ETH10G_B1_RX_LOS: J5.8(RX_ LOS) R27.2(B<0>)
ETH10G_B1_RXN: J5.12(RD*) J7.E1
ETH10G_B1_RXP: J5.13(RD_P) J7.D1
ETH10G_B1_SCL: J5.5(SCL) J7.E3 R28.2(B<0>)
ETH10G_B1_SDA: J5.4(SDA) J7.D3 R26.2(B<0>)
ETH10G_B1_TX_DIS: J5.3(TX_DISABLE) R20.2(B<0>) R21.1(A<0>)
ETH10G_B1_TX_FAULT: J5.2(TX_FAULT) R18.2(B<0>)
ETH10G_B1_TXN: J5.19(TD*) J7.H1
ETH10G_B1_TXP: J5.18(TD_P) J7.G1
ETH10G_B2_MOD_ABS: J17.6(MOD_ABS) R43.2(B<0>) R57.1(A<0>)
ETH10G_B2_PRES_N: J19.I2 R43.1(A<0>)
ETH10G_B2_RS0: J17.7(RS0) R50.2(B<0>) R51.1(A<0>)
ETH10G_B2_RS1: J17.9(RS1) R52.2(B<0>) R53.1(A<0>)
ETH10G_B2_RX_LOS: J17.8(RX_ LOS) R55.2(B<0>)
ETH10G_B2_RXN: J17.12(RD*) J19.E1
ETH10G_B2_RXP: J17.13(RD_P) J19.D1
ETH10G_B2_SCL: J17.5(SCL) J19.E3 R56.2(B<0>)
ETH10G_B2_SDA: J17.4(SDA) J19.D3 R54.2(B<0>)
ETH10G_B2_TX_DIS: J17.3(TX_DISABLE) R48.2(B<0>) R49.1(A<0>)
ETH10G_B2_TX_FAULT: J17.2(TX_FAULT) R46.2(B<0>)
ETH10G_B2_TXN: J17.19(TD*) J19.H1
ETH10G_B2_TXP: J17.18(TD_P) J19.G1
ETH40G_B1_INT_N: J8.28(INT*) R78.2(B<0>)
ETH40G_B1_LPMODE: J8.31(LPMODE) R79.1(A<0>) R84.2(B<0>)
ETH40G_B1_MODPRS_N: J8.27(MODPRS*) R80.1(A<0>)
ETH40G_B1_MODSEL_N: J8.8(MODSEL*) R76.2(B<0>) R77.1(A<0>)
ETH40G_B1_PRES_N: J7.H5 R80.2(B<0>)
ETH40G_B1_RESET_N: J8.9(RESET*) R75.2(B<0>) R83.2(B<0>)
ETH40G_B1_RX0N: J7.F6 J8.18(RX1*)
ETH40G_B1_RX0P: J7.E6 J8.17(RX1_P)
ETH40G_B1_RX1N: J7.B5 J8.21(RX2*)
ETH40G_B1_RX1P: J7.A5 J8.22(RX2_P)
ETH40G_B1_RX2N: J7.B3 J8.15(RX3*)
ETH40G_B1_RX2P: J7.A3 J8.14(RX3_P)
ETH40G_B1_RX3N: J7.C2 J8.24(RX4*)
ETH40G_B1_RX3P: J7.B2 J8.25(RX4_P)
ETH40G_B1_SCL: J7.F4 J8.11(SCL) R82.2(B<0>)
ETH40G_B1_SDA: J7.E4 J8.12(SDA) R81.2(B<0>)
ETH40G_B1_TX0N: J7.I6 J8.37(TX1*)
ETH40G_B1_TX0P: J7.H6 J8.36(TX1_P)
ETH40G_B1_TX1N: J7.C6 J8.2(TX2*)
ETH40G_B1_TX1P: J7.B6 J8.3(TX2_P)
ETH40G_B1_TX2N: J7.C4 J8.34(TX3*)
ETH40G_B1_TX2P: J7.B4 J8.33(TX3_P)
ETH40G_B1_TX3N: J7.B1 J8.5(TX4*)
ETH40G_B1_TX3P: J7.A1 J8.6(TX4_P)
ETH40G_B2_INT_N: J20.28(INT*) R64.2(B<0>)
ETH40G_B2_LPMODE: J20.31(LPMODE) R65.1(A<0>) R70.2(B<0>)
ETH40G_B2_MODPRS_N: J20.27(MODPRS*) R66.1(A<0>)
ETH40G_B2_MODSEL_N: J20.8(MODSEL*) R62.2(B<0>) R63.1(A<0>)
ETH40G_B2_PRES_N: J19.H5 R66.2(B<0>)
ETH40G_B2_RESET_N: J20.9(RESET*) R61.2(B<0>) R69.2(B<0>)
ETH40G_B2_RX0N: J19.F6 J20.18(RX1*)
ETH40G_B2_RX0P: J19.E6 J20.17(RX1_P)
ETH40G_B2_RX1N: J19.B5 J20.21(RX2*)
ETH40G_B2_RX1P: J19.A5 J20.22(RX2_P)
ETH40G_B2_RX2N: J19.B3 J20.15(RX3*)
ETH40G_B2_RX2P: J19.A3 J20.14(RX3_P)
ETH40G_B2_RX3N: J19.C2 J20.24(RX4*)
ETH40G_B2_RX3P: J19.B2 J20.25(RX4_P)
ETH40G_B2_SCL: J19.F4 J20.11(SCL) R68.2(B<0>)
ETH40G_B2_SDA: J19.E4 J20.12(SDA) R67.2(B<0>)
ETH40G_B2_TX0N: J19.I6 J20.37(TX1*)
ETH40G_B2_TX0P: J19.H6 J20.36(TX1_P)
ETH40G_B2_TX1N: J19.C6 J20.2(TX2*)
ETH40G_B2_TX1P: J19.B6 J20.3(TX2_P)
ETH40G_B2_TX2N: J19.C4 J20.34(TX3*)
ETH40G_B2_TX2P: J19.B4 J20.33(TX3_P)
ETH40G_B2_TX3N: J19.B1 J20.5(TX4*)
ETH40G_B2_TX3P: J19.A1 J20.6(TX4_P)
JBOD_B1_MATED_N: J11.B4 R1.2(B<0>)
JBOD_B2_MATED_N: J23.B4 R71.2(B<0>)
MEZZ_B1_EN: J1.H5 J2.157
MEZZ_B1_SCL: J1.G5 J2.156
MEZZ_B1_SDA: J1.I4 J2.158
MEZZ_B2_EN: J13.H5 J14.157
MEZZ_B2_SCL: J13.G5 J14.156
MEZZ_B2_SDA: J13.I4 J14.158
MEZZ_PRESENT_B1_N: J1.H6 J2.160
MEZZ_PRESENT_B2_N: J13.H6 J14.160
PCIE_B2T_B1_TX_DN<0>: J1.L8 J2.125
PCIE_B2T_B1_TX_DN<1>: J1.K7 J2.110
PCIE_B2T_B1_TX_DN<2>: J1.L6 J2.93
PCIE_B2T_B1_TX_DN<3>: J1.K5 J2.78
PCIE_B2T_B1_TX_DN<4>: J1.L4 J2.61
PCIE_B2T_B1_TX_DN<5>: J1.K3 J2.46
PCIE_B2T_B1_TX_DN<6>: J1.L2 J2.29
PCIE_B2T_B1_TX_DN<7>: J1.K1 J2.14
PCIE_B2T_B1_TX_DN<8>: J1.O8 J2.127
PCIE_B2T_B1_TX_DN<9>: J1.N7 J2.112
PCIE_B2T_B1_TX_DN<10>: J1.O6 J2.95
PCIE_B2T_B1_TX_DN<11>: J1.N5 J2.80
PCIE_B2T_B1_TX_DN<12>: J1.O4 J2.63
PCIE_B2T_B1_TX_DN<13>: J1.N3 J2.48
PCIE_B2T_B1_TX_DN<14>: J1.O2 J2.31
PCIE_B2T_B1_TX_DN<15>: J1.N1 J2.16
PCIE_B2T_B1_TX_DP<0>: J1.K8 J2.117
PCIE_B2T_B1_TX_DP<1>: J1.J7 J2.102
PCIE_B2T_B1_TX_DP<2>: J1.K6 J2.85
PCIE_B2T_B1_TX_DP<3>: J1.J5 J2.70
PCIE_B2T_B1_TX_DP<4>: J1.K4 J2.53
PCIE_B2T_B1_TX_DP<5>: J1.J3 J2.38
PCIE_B2T_B1_TX_DP<6>: J1.K2 J2.21
PCIE_B2T_B1_TX_DP<7>: J1.J1 J2.6
PCIE_B2T_B1_TX_DP<8>: J1.N8 J2.119
PCIE_B2T_B1_TX_DP<9>: J1.M7 J2.104
PCIE_B2T_B1_TX_DP<10>: J1.N6 J2.87
PCIE_B2T_B1_TX_DP<11>: J1.M5 J2.72
PCIE_B2T_B1_TX_DP<12>: J1.N4 J2.55
PCIE_B2T_B1_TX_DP<13>: J1.M3 J2.40
PCIE_B2T_B1_TX_DP<14>: J1.N2 J2.23
PCIE_B2T_B1_TX_DP<15>: J1.M1 J2.8
PCIE_B2T_B2_TX_DN<0>: J13.L8 J14.125
PCIE_B2T_B2_TX_DN<1>: J13.K7 J14.110
PCIE_B2T_B2_TX_DN<2>: J13.L6 J14.93
PCIE_B2T_B2_TX_DN<3>: J13.K5 J14.78
PCIE_B2T_B2_TX_DN<4>: J13.L4 J14.61
PCIE_B2T_B2_TX_DN<5>: J13.K3 J14.46
PCIE_B2T_B2_TX_DN<6>: J13.L2 J14.29
PCIE_B2T_B2_TX_DN<7>: J13.K1 J14.14
PCIE_B2T_B2_TX_DN<8>: J13.O8 J14.127
PCIE_B2T_B2_TX_DN<9>: J13.N7 J14.112
PCIE_B2T_B2_TX_DN<10>: J13.O6 J14.95
PCIE_B2T_B2_TX_DN<11>: J13.N5 J14.80
PCIE_B2T_B2_TX_DN<12>: J13.O4 J14.63
PCIE_B2T_B2_TX_DN<13>: J13.N3 J14.48
PCIE_B2T_B2_TX_DN<14>: J13.O2 J14.31
PCIE_B2T_B2_TX_DN<15>: J13.N1 J14.16
PCIE_B2T_B2_TX_DP<0>: J13.K8 J14.117
PCIE_B2T_B2_TX_DP<1>: J13.J7 J14.102
PCIE_B2T_B2_TX_DP<2>: J13.K6 J14.85
PCIE_B2T_B2_TX_DP<3>: J13.J5 J14.70
PCIE_B2T_B2_TX_DP<4>: J13.K4 J14.53
PCIE_B2T_B2_TX_DP<5>: J13.J3 J14.38
PCIE_B2T_B2_TX_DP<6>: J13.K2 J14.21
PCIE_B2T_B2_TX_DP<7>: J13.J1 J14.6
PCIE_B2T_B2_TX_DP<8>: J13.N8 J14.119
PCIE_B2T_B2_TX_DP<9>: J13.M7 J14.104
PCIE_B2T_B2_TX_DP<10>: J13.N6 J14.87
PCIE_B2T_B2_TX_DP<11>: J13.M5 J14.72
PCIE_B2T_B2_TX_DP<12>: J13.N4 J14.55
PCIE_B2T_B2_TX_DP<13>: J13.M3 J14.40
PCIE_B2T_B2_TX_DP<14>: J13.N2 J14.23
PCIE_B2T_B2_TX_DP<15>: J13.M1 J14.8
PCIE_CFG_B1_ID0: J1.G3 J2.149
PCIE_CFG_B1_ID1: J1.H3 J2.148
PCIE_CFG_B2_ID0: J13.G3 J14.149
PCIE_CFG_B2_ID1: J13.H3 J14.148
PCIE_RESET_B1_N<0>: J1.I2 J2.150
PCIE_RESET_B1_N<1>: J1.H2 J2.151
PCIE_RESET_B1_N<2>: J1.H1 J2.143
PCIE_RESET_B1_N<3>: J1.G1 J2.152
PCIE_RESET_B2_N<0>: J13.I2 J14.150
PCIE_RESET_B2_N<1>: J13.H2 J14.151
PCIE_RESET_B2_N<2>: J13.H1 J14.143
PCIE_RESET_B2_N<3>: J13.G1 J14.152
PCIE_T2B_B1_RX_DN<0>: J1.C8 J2.121
PCIE_T2B_B1_RX_DN<1>: J1.B7 J2.106
PCIE_T2B_B1_RX_DN<2>: J1.C6 J2.89
PCIE_T2B_B1_RX_DN<3>: J1.B5 J2.74
PCIE_T2B_B1_RX_DN<4>: J1.C4 J2.57
PCIE_T2B_B1_RX_DN<5>: J1.B3 J2.42
PCIE_T2B_B1_RX_DN<6>: J1.C2 J2.25
PCIE_T2B_B1_RX_DN<7>: J1.B1 J2.10
PCIE_T2B_B1_RX_DN<8>: J1.F8 J2.123
PCIE_T2B_B1_RX_DN<9>: J1.E7 J2.108
PCIE_T2B_B1_RX_DN<10>: J1.F6 J2.91
PCIE_T2B_B1_RX_DN<11>: J1.E5 J2.76
PCIE_T2B_B1_RX_DN<12>: J1.F4 J2.59
PCIE_T2B_B1_RX_DN<13>: J1.E3 J2.44
PCIE_T2B_B1_RX_DN<14>: J1.F2 J2.27
PCIE_T2B_B1_RX_DN<15>: J1.E1 J2.12
PCIE_T2B_B1_RX_DP<0>: J1.B8 J2.113
PCIE_T2B_B1_RX_DP<1>: J1.A7 J2.98
PCIE_T2B_B1_RX_DP<2>: J1.B6 J2.81
PCIE_T2B_B1_RX_DP<3>: J1.A5 J2.66
PCIE_T2B_B1_RX_DP<4>: J1.B4 J2.49
PCIE_T2B_B1_RX_DP<5>: J1.A3 J2.34
PCIE_T2B_B1_RX_DP<6>: J1.B2 J2.17
PCIE_T2B_B1_RX_DP<7>: J1.A1 J2.2
PCIE_T2B_B1_RX_DP<8>: J1.E8 J2.115
PCIE_T2B_B1_RX_DP<9>: J1.D7 J2.100
PCIE_T2B_B1_RX_DP<10>: J1.E6 J2.83
PCIE_T2B_B1_RX_DP<11>: J1.D5 J2.68
PCIE_T2B_B1_RX_DP<12>: J1.E4 J2.51
PCIE_T2B_B1_RX_DP<13>: J1.D3 J2.36
PCIE_T2B_B1_RX_DP<14>: J1.E2 J2.19
PCIE_T2B_B1_RX_DP<15>: J1.D1 J2.4
PCIE_T2B_B2_RX_DN<0>: J13.C8 J14.121
PCIE_T2B_B2_RX_DN<1>: J13.B7 J14.106
PCIE_T2B_B2_RX_DN<2>: J13.C6 J14.89
PCIE_T2B_B2_RX_DN<3>: J13.B5 J14.74
PCIE_T2B_B2_RX_DN<4>: J13.C4 J14.57
PCIE_T2B_B2_RX_DN<5>: J13.B3 J14.42
PCIE_T2B_B2_RX_DN<6>: J13.C2 J14.25
PCIE_T2B_B2_RX_DN<7>: J13.B1 J14.10
PCIE_T2B_B2_RX_DN<8>: J13.F8 J14.123
PCIE_T2B_B2_RX_DN<9>: J13.E7 J14.108
PCIE_T2B_B2_RX_DN<10>: J13.F6 J14.91
PCIE_T2B_B2_RX_DN<11>: J13.E5 J14.76
PCIE_T2B_B2_RX_DN<12>: J13.F4 J14.59
PCIE_T2B_B2_RX_DN<13>: J13.E3 J14.44
PCIE_T2B_B2_RX_DN<14>: J13.F2 J14.27
PCIE_T2B_B2_RX_DN<15>: J13.E1 J14.12
PCIE_T2B_B2_RX_DP<0>: J13.B8 J14.113
PCIE_T2B_B2_RX_DP<1>: J13.A7 J14.98
PCIE_T2B_B2_RX_DP<2>: J13.B6 J14.81
PCIE_T2B_B2_RX_DP<3>: J13.A5 J14.66
PCIE_T2B_B2_RX_DP<4>: J13.B4 J14.49
PCIE_T2B_B2_RX_DP<5>: J13.A3 J14.34
PCIE_T2B_B2_RX_DP<6>: J13.B2 J14.17
PCIE_T2B_B2_RX_DP<7>: J13.A1 J14.2
PCIE_T2B_B2_RX_DP<8>: J13.E8 J14.115
PCIE_T2B_B2_RX_DP<9>: J13.D7 J14.100
PCIE_T2B_B2_RX_DP<10>: J13.E6 J14.83
PCIE_T2B_B2_RX_DP<11>: J13.D5 J14.68
PCIE_T2B_B2_RX_DP<12>: J13.E4 J14.51
PCIE_T2B_B2_RX_DP<13>: J13.D3 J14.36
PCIE_T2B_B2_RX_DP<14>: J13.E2 J14.19
PCIE_T2B_B2_RX_DP<15>: J13.D1 J14.4
PCIE_WAKE_B1_N: J1.H4 J2.159
PCIE_WAKE_B2_N: J13.H4 J14.159
PSU_B1_ALERT_N: J1.H7 J7.G5 J26.1(IO<1>) U1.S4
PSU_B2_ALERT_N: J13.H7 J19.G5 J29.1(IO<1>) U1.S9
SAS_B1_RX1N: J11.E1 J12.1B5
SAS_B1_RX1P: J11.D1 J12.1B4
SAS_B1_RX2N: J11.I2 J12.1A5
SAS_B1_RX2P: J11.H2 J12.1A4
SAS_B1_RX3N: J11.C2 J12.1B8
SAS_B1_RX3P: J11.B2 J12.1B7
SAS_B1_RX4N: J11.E3 J12.1A8
SAS_B1_RX4P: J11.D3 J12.1A7
SAS_B1_RX5N: J11.I4 J12.2B5
SAS_B1_RX5P: J11.H4 J12.2B4
SAS_B1_RX6N: J11.E5 J12.2A5
SAS_B1_RX6P: J11.D5 J12.2A4
SAS_B1_RX7N: J11.I6 J12.2B8
SAS_B1_RX7P: J11.H6 J12.2B7
SAS_B1_RX8N: J11.C6 J12.2A8
SAS_B1_RX8P: J11.B6 J12.2A7
SAS_B1_TX1N: J11.B1 J12.1D5
SAS_B1_TX1P: J11.A1 J12.1D4
SAS_B1_TX2N: J11.H1 J12.1C5
SAS_B1_TX2P: J11.G1 J12.1C4
SAS_B1_TX3N: J11.F2 J12.1D8
SAS_B1_TX3P: J11.E2 J12.1D7
SAS_B1_TX4N: J11.H3 J12.1C8
SAS_B1_TX4P: J11.G3 J12.1C7
SAS_B1_TX5N: J11.F4 J12.2D5
SAS_B1_TX5P: J11.E4 J12.2D4
SAS_B1_TX6N: J11.B5 J12.2C5
SAS_B1_TX6P: J11.A5 J12.2C4
SAS_B1_TX7N: J11.H5 J12.2D8
SAS_B1_TX7P: J11.G5 J12.2D7
SAS_B1_TX8N: J11.F6 J12.2C8
SAS_B1_TX8P: J11.E6 J12.2C7
SAS_B2_RX1N: J23.E1 J24.1B5
SAS_B2_RX1P: J23.D1 J24.1B4
SAS_B2_RX2N: J23.I2 J24.1A5
SAS_B2_RX2P: J23.H2 J24.1A4
SAS_B2_RX3N: J23.C2 J24.1B8
SAS_B2_RX3P: J23.B2 J24.1B7
SAS_B2_RX4N: J23.E3 J24.1A8
SAS_B2_RX4P: J23.D3 J24.1A7
SAS_B2_RX5N: J23.I4 J24.2B5
SAS_B2_RX5P: J23.H4 J24.2B4
SAS_B2_RX6N: J23.E5 J24.2A5
SAS_B2_RX6P: J23.D5 J24.2A4
SAS_B2_RX7N: J23.I6 J24.2B8
SAS_B2_RX7P: J23.H6 J24.2B7
SAS_B2_RX8N: J23.C6 J24.2A8
SAS_B2_RX8P: J23.B6 J24.2A7
SAS_B2_TX1N: J23.B1 J24.1D5
SAS_B2_TX1P: J23.A1 J24.1D4
SAS_B2_TX2N: J23.H1 J24.1C5
SAS_B2_TX2P: J23.G1 J24.1C4
SAS_B2_TX3N: J23.F2 J24.1D8
SAS_B2_TX3P: J23.E2 J24.1D7
SAS_B2_TX4N: J23.H3 J24.1C8
